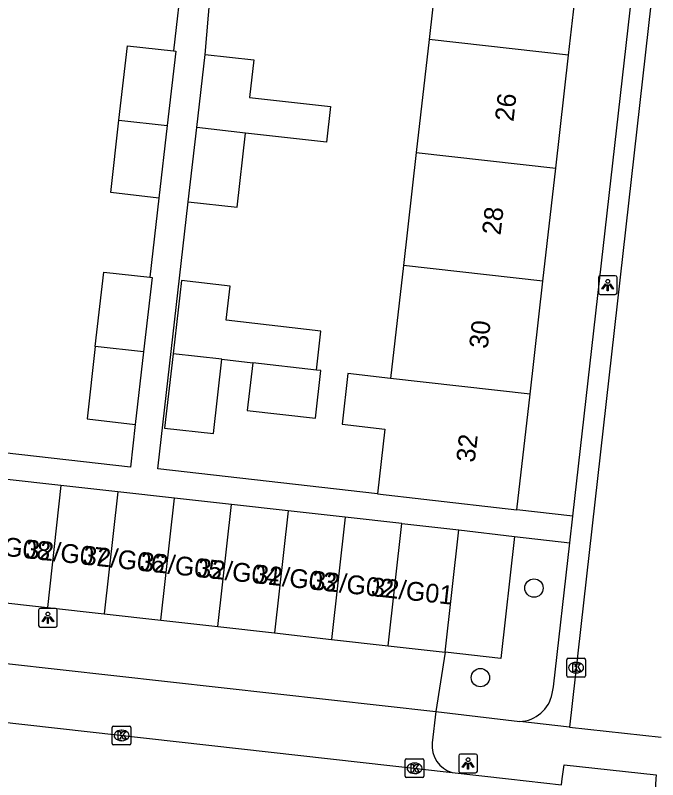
# Model space of a CAD drawing. Extents: x 161928 to 163055, y 386475 to 387428.
# Drawn here: x 162100.36 to 162134.62, y 386749.95 to 386790.68 of the extents above; entities that cross this region are included whole.
import ezdxf

# ---------------------------------------------------------------- set-up
doc = ezdxf.new("R2010")
doc.units = 0
for name, color, linetype in [('IMGEO_Boom', 7, 'Continuous'), ('IMGEO_Groenvoorziening', 7, 'Continuous'), ('IMGEO_Kolk', 7, 'Continuous'), ('IMGEO_Lichtpunt', 7, 'Continuous'), ('IMGEO_Pand', 7, 'Continuous'), ('IMGEO_Pand_nummerreeks', 7, 'Continuous'), ('IMGEO_Rijbaan_lokaal_open', 7, 'Continuous'), ('IMGEO_Voetpad_open', 7, 'Continuous')]:
    doc.layers.add(name, color=color, linetype=linetype)

msp = doc.modelspace()

# ---------------------------------------------------------------- linework, layer by layer
at = {"layer": 'IMGEO_Boom'}
for centre in [(162128.021, 386760.164), (162125.163, 386755.392)]:
    msp.add_circle(centre, 0.489, dxfattribs=at)
at = {"layer": 'IMGEO_Groenvoorziening'}
msp.add_lwpolyline([(162126.988, 386762.92), (162126.263, 386756.411), (162123.283, 386756.757)], dxfattribs=at)
at = {"layer": 'IMGEO_Kolk'}
for p, q in [((162129.77, 386755.497), (162129.77, 386756.349)), ((162129.845, 386756.423), (162130.697, 386756.423)), ((162130.258, 386756.203), (162130.283, 386756.203)), ((162130.771, 386756.349), (162130.771, 386755.497)), ((162130.697, 386755.423), (162129.845, 386755.423)), ((162130.281, 386755.643), (162130.256, 386755.643)), ((162105.606, 386752.814), (162106.458, 386752.814)), ((162105.531, 386751.888), (162105.531, 386752.74)), ((162106.019, 386752.594), (162106.044, 386752.594)), ((162106.532, 386752.74), (162106.532, 386751.888)), ((162106.042, 386752.034), (162106.017, 386752.034)), ((162106.458, 386751.814), (162105.606, 386751.814)), ((162121.155, 386750.138), (162121.155, 386750.99)), ((162121.23, 386751.064), (162122.082, 386751.064)), ((162121.643, 386750.844), (162121.668, 386750.844)), ((162122.156, 386750.99), (162122.156, 386750.138)), ((162122.082, 386750.064), (162121.23, 386750.064)), ((162121.666, 386750.284), (162121.641, 386750.284))]:
    msp.add_line(p, q, dxfattribs=at)
for points in [[(162129.77, 386755.497), (162129.77, 386756.349)], [(162129.845, 386756.423), (162130.697, 386756.423)], [(162130.091, 386756.123), (162130.214, 386756.123), (162130.214, 386755.972), (162130.344, 386756.123), (162130.508, 386756.123), (162130.362, 386755.972), (162130.515, 386755.723), (162130.363, 386755.723), (162130.278, 386755.887), (162130.214, 386755.82), (162130.214, 386755.723), (162130.091, 386755.723), (162130.091, 386756.123)], [(162130.771, 386756.349), (162130.771, 386755.497)], [(162130.697, 386755.423), (162129.845, 386755.423)], [(162105.606, 386752.814), (162106.458, 386752.814)], [(162105.531, 386751.888), (162105.531, 386752.74)], [(162105.852, 386752.514), (162105.975, 386752.514), (162105.975, 386752.363), (162106.105, 386752.514), (162106.269, 386752.514), (162106.123, 386752.363), (162106.276, 386752.114), (162106.124, 386752.114), (162106.039, 386752.278), (162105.975, 386752.211), (162105.975, 386752.114), (162105.852, 386752.114), (162105.852, 386752.514)], [(162106.532, 386752.74), (162106.532, 386751.888)], [(162106.458, 386751.814), (162105.606, 386751.814)], [(162121.155, 386750.138), (162121.155, 386750.99)], [(162121.23, 386751.064), (162122.082, 386751.064)], [(162121.476, 386750.764), (162121.599, 386750.764), (162121.599, 386750.613), (162121.729, 386750.764), (162121.893, 386750.764), (162121.747, 386750.613), (162121.9, 386750.364), (162121.748, 386750.364), (162121.663, 386750.528), (162121.599, 386750.461), (162121.599, 386750.364), (162121.476, 386750.364), (162121.476, 386750.764)], [(162122.156, 386750.99), (162122.156, 386750.138)], [(162122.082, 386750.064), (162121.23, 386750.064)]]:
    msp.add_lwpolyline(points, dxfattribs=at)
for centre, start, end in [((162129.847, 386756.347), 91.552, 178.448), ((162129.847, 386756.347), 91.552, 178.448), ((162130.695, 386756.347), 1.552, 88.448), ((162130.695, 386756.347), 1.552, 88.448), ((162129.847, 386755.499), 181.552, 268.448), ((162129.847, 386755.499), 181.552, 268.448), ((162130.695, 386755.499), 271.552, 358.448), ((162130.695, 386755.499), 271.552, 358.448), ((162105.608, 386752.738), 91.552, 178.448), ((162105.608, 386752.738), 91.552, 178.448), ((162106.456, 386752.738), 1.552, 88.448), ((162106.456, 386752.738), 1.552, 88.448), ((162105.608, 386751.89), 181.552, 268.448), ((162105.608, 386751.89), 181.552, 268.448), ((162106.456, 386751.89), 271.552, 358.448), ((162106.456, 386751.89), 271.552, 358.448), ((162121.232, 386750.988), 91.552, 178.448), ((162121.232, 386750.988), 91.552, 178.448), ((162122.08, 386750.988), 1.552, 88.448), ((162122.08, 386750.988), 1.552, 88.448), ((162121.232, 386750.14), 181.552, 268.448), ((162121.232, 386750.14), 181.552, 268.448), ((162122.08, 386750.14), 271.552, 358.448), ((162122.08, 386750.14), 271.552, 358.448)]:
    msp.add_arc(centre, 0.0765, start, end, dxfattribs=at)
for centre, major_axis, ratio, start_param, end_param in [((162130.257, 386755.923), (-0.387, 0.002), 0.722429, 4.712389, 7.853982), ((162130.282, 386755.923), (-0.39, 0.002), 0.717154, 1.570796, 4.712389), ((162106.018, 386752.314), (-0.387, 0.002), 0.722429, 4.712389, 7.853982), ((162106.043, 386752.314), (-0.39, 0.002), 0.717154, 1.570796, 4.712389), ((162121.642, 386750.564), (-0.387, 0.002), 0.722429, 4.712389, 7.853982), ((162121.667, 386750.564), (-0.39, 0.002), 0.717154, 1.570796, 4.712389)]:
    msp.add_ellipse(centre, major_axis=major_axis, ratio=ratio, start_param=start_param, end_param=end_param, dxfattribs=at)
at = {"layer": 'IMGEO_Lichtpunt'}
for p, q in [((162131.457, 386776.71), (162131.457, 386775.903)), ((162131.457, 386776.71), (162131.457, 386775.903)), ((162132.359, 386776.805), (162131.551, 386776.805)), ((162132.359, 386776.805), (162131.551, 386776.805)), ((162132.453, 386775.903), (162132.453, 386776.71)), ((162132.453, 386775.903), (162132.453, 386776.71)), ((162131.551, 386775.809), (162132.359, 386775.809)), ((162131.551, 386775.809), (162132.359, 386775.809)), ((162101.601, 386758.985), (162101.601, 386758.178)), ((162101.601, 386758.985), (162101.601, 386758.178)), ((162102.503, 386759.08), (162101.695, 386759.08)), ((162102.503, 386759.08), (162101.695, 386759.08)), ((162102.597, 386758.178), (162102.597, 386758.985)), ((162102.597, 386758.178), (162102.597, 386758.985)), ((162101.695, 386758.084), (162102.503, 386758.084)), ((162101.695, 386758.084), (162102.503, 386758.084)), ((162124.009, 386751.224), (162124.009, 386750.417)), ((162124.009, 386751.224), (162124.009, 386750.417)), ((162124.911, 386751.319), (162124.103, 386751.319)), ((162124.911, 386751.319), (162124.103, 386751.319)), ((162125.005, 386750.417), (162125.005, 386751.224)), ((162125.005, 386750.417), (162125.005, 386751.224)), ((162124.103, 386750.323), (162124.911, 386750.323)), ((162124.103, 386750.323), (162124.911, 386750.323))]:
    msp.add_line(p, q, dxfattribs=at)
for points in [[(162131.831, 386776.374), (162131.87, 386776.346), (162131.682, 386776.084), (162131.644, 386776.111), (162131.831, 386776.374)], [(162131.933, 386776.326), (162131.98, 386776.326), (162131.98, 386776.004), (162131.933, 386776.004), (162131.933, 386776.326)], [(162132.043, 386776.346), (162132.081, 386776.373), (162132.268, 386776.111), (162132.229, 386776.083), (162132.043, 386776.346)], [(162101.975, 386758.649), (162102.014, 386758.621), (162101.826, 386758.359), (162101.788, 386758.386), (162101.975, 386758.649)], [(162102.077, 386758.601), (162102.124, 386758.601), (162102.124, 386758.279), (162102.077, 386758.279), (162102.077, 386758.601)], [(162102.187, 386758.621), (162102.225, 386758.648), (162102.412, 386758.386), (162102.373, 386758.358), (162102.187, 386758.621)], [(162124.383, 386750.888), (162124.422, 386750.86), (162124.234, 386750.598), (162124.196, 386750.625), (162124.383, 386750.888)], [(162124.485, 386750.84), (162124.532, 386750.84), (162124.532, 386750.518), (162124.485, 386750.518), (162124.485, 386750.84)], [(162124.595, 386750.86), (162124.633, 386750.887), (162124.82, 386750.625), (162124.781, 386750.597), (162124.595, 386750.86)]]:
    msp.add_lwpolyline(points, dxfattribs=at)
for centre in [(162131.956, 386776.508), (162102.1, 386758.783), (162124.508, 386751.022)]:
    msp.add_circle(centre, 0.0994, dxfattribs=at)
for centre, start, end in [((162131.551, 386776.71), 90, 180), ((162131.551, 386776.71), 90, 180), ((162132.359, 386776.71), 0, 90), ((162132.359, 386776.71), 0, 90), ((162131.551, 386775.903), 180, 270), ((162131.551, 386775.903), 180, 270), ((162132.359, 386775.903), 270, 0), ((162132.359, 386775.903), 270, 360), ((162101.695, 386758.985), 90, 180), ((162101.695, 386758.985), 90, 180), ((162102.503, 386758.985), 0, 90), ((162102.503, 386758.985), 0, 90), ((162101.695, 386758.178), 180, 270), ((162101.695, 386758.178), 180, 270), ((162102.503, 386758.178), 270, 0), ((162102.503, 386758.178), 270, 360), ((162124.103, 386751.224), 90, 180), ((162124.103, 386751.224), 90, 180), ((162124.911, 386751.224), 0, 90), ((162124.911, 386751.224), 0, 90), ((162124.103, 386750.417), 180, 270), ((162124.103, 386750.417), 180, 270), ((162124.911, 386750.417), 270, 0), ((162124.911, 386750.417), 270, 360)]:
    msp.add_arc(centre, 0.0946, start, end, dxfattribs=at)
at = {"layer": 'IMGEO_Pand'}
for points in [[(162123.11, 386795.42), (162122.426, 386789.399)], [(162129.868, 386788.553), (162130.552, 386794.574)], [(162105.891, 386785.102), (162106.342, 386789.062), (162108.805, 386788.782)], [(162122.426, 386789.399), (162121.742, 386783.377)], [(162129.868, 386788.553), (162122.426, 386789.399)], [(162108.805, 386788.782), (162108.915, 386788.769), (162108.464, 386784.81)], [(162110.035, 386784.706), (162110.479, 386788.602)], [(162110.479, 386788.602), (162113.084, 386788.305), (162112.857, 386786.306), (162117.166, 386785.817), (162116.951, 386783.92), (162112.641, 386784.41)], [(162129.183, 386782.531), (162129.868, 386788.553)], [(162108.024, 386780.945), (162105.451, 386781.238), (162105.891, 386785.102)], [(162105.891, 386785.102), (162108.464, 386784.81)], [(162108.464, 386784.81), (162108.024, 386780.945)], [(162109.585, 386780.749), (162110.035, 386784.706)], [(162112.641, 386784.41), (162110.035, 386784.706)], [(162109.585, 386780.749), (162112.19, 386780.452), (162112.641, 386784.41)], [(162121.742, 386783.377), (162121.057, 386777.355)], [(162121.742, 386783.377), (162129.183, 386782.531)], [(162128.499, 386776.51), (162129.183, 386782.531)], [(162121.057, 386777.355), (162120.373, 386771.335)], [(162128.499, 386776.51), (162121.057, 386777.355)], [(162104.629, 386773.043), (162105.08, 386777.003), (162107.543, 386776.723)], [(162107.543, 386776.723), (162107.653, 386776.71), (162107.202, 386772.751)], [(162116.426, 386771.779), (162116.662, 386773.859), (162111.616, 386774.432), (162111.822, 386776.247), (162109.217, 386776.544), (162108.773, 386772.648)], [(162127.815, 386770.489), (162128.499, 386776.51)], [(162104.629, 386773.043), (162104.189, 386769.179), (162106.762, 386768.886)], [(162107.202, 386772.751), (162104.629, 386773.043)], [(162107.202, 386772.751), (162106.762, 386768.886)], [(162108.773, 386772.648), (162108.323, 386768.691), (162110.928, 386768.394), (162111.379, 386772.352)], [(162111.379, 386772.352), (162108.773, 386772.648)], [(162111.379, 386772.352), (162113.021, 386772.166)], [(162113.021, 386772.166), (162112.733, 386769.634), (162116.374, 386769.22), (162116.662, 386771.752), (162116.426, 386771.779)], [(162116.426, 386771.779), (162113.021, 386772.166)], [(162120.373, 386771.335), (162118.098, 386771.594), (162117.791, 386768.89), (162120.066, 386768.631), (162119.674, 386765.185)], [(162127.815, 386770.489), (162120.373, 386771.335)], [(162127.116, 386764.34), (162127.815, 386770.489)], [(162102.798, 386765.637), (162099.767, 386765.974)], [(162102.798, 386765.637), (162102.071, 386759.122)], [(162105.828, 386765.299), (162102.798, 386765.637)], [(162105.828, 386765.299), (162105.102, 386758.784)], [(162108.858, 386764.961), (162105.828, 386765.299)], [(162119.674, 386765.185), (162122.148, 386764.904), (162127.116, 386764.34)], [(162108.132, 386758.446), (162108.858, 386764.961)], [(162111.888, 386764.623), (162108.858, 386764.961)], [(162111.162, 386758.109), (162111.888, 386764.623)], [(162114.918, 386764.285), (162111.888, 386764.623)], [(162114.918, 386764.285), (162114.192, 386757.771)], [(162117.949, 386763.948), (162114.918, 386764.285)], [(162117.949, 386763.948), (162117.222, 386757.433)], [(162120.979, 386763.61), (162117.949, 386763.948)], [(162120.253, 386757.095), (162120.979, 386763.61)], [(162120.979, 386763.61), (162124.009, 386763.272)], [(162123.283, 386756.757), (162124.009, 386763.272)], [(162099.041, 386759.46), (162102.071, 386759.122)], [(162102.071, 386759.122), (162105.102, 386758.784)], [(162105.102, 386758.784), (162108.132, 386758.446)], [(162108.132, 386758.446), (162111.162, 386758.109)], [(162111.162, 386758.109), (162114.192, 386757.771)], [(162114.192, 386757.771), (162117.222, 386757.433)], [(162117.222, 386757.433), (162120.253, 386757.095)], [(162120.253, 386757.095), (162123.283, 386756.757)]]:
    msp.add_lwpolyline(points, dxfattribs=at)
at = {"layer": 'IMGEO_Rijbaan_lokaal_open'}
for points in [[(162136.354, 386809.876), (162129.914, 386752.746)], [(162086.964, 386754.512), (162089.619, 386754.158), (162123.662, 386750.337)], [(162129.914, 386752.746), (162134.807, 386752.229)], [(162123.662, 386750.337), (162126.661, 386750), (162129.491, 386749.686)]]:
    msp.add_lwpolyline(points, dxfattribs=at)
at = {"layer": 'IMGEO_Voetpad_open'}
for points in [[(162130.092, 386764.003), (162135.581, 386812.449)], [(162109.286, 386793.003), (162108.805, 386788.782)], [(162110.479, 386788.602), (162110.847, 386792.808)], [(162108.024, 386780.945), (162107.543, 386776.723)], [(162119.674, 386765.185), (162107.966, 386766.515), (162109.585, 386780.749)], [(162106.762, 386768.886), (162106.503, 386766.612), (162094.742, 386767.943)], [(162130.092, 386764.003), (162127.116, 386764.34)], [(162129.93, 386762.572), (162130.092, 386764.003)], [(162124.009, 386763.272), (162126.988, 386762.92)], [(162126.988, 386762.92), (162129.93, 386762.572)], [(162128.987, 386754.54), (162129.066, 386754.9), (162129.93, 386762.572)], [(162088.426, 386757.42), (162122.784, 386753.584)], [(162123.283, 386756.757), (162122.784, 386753.584)], [(162122.784, 386753.584), (162122.596, 386751.923)], [(162122.784, 386753.584), (162127.26, 386753.058)], [(162129.914, 386752.746), (162127.26, 386753.058)], [(162129.491, 386749.686), (162129.532, 386750), (162129.629, 386750.754), (162134.53, 386750.22), (162134.518, 386750), (162134.473, 386749.133)]]:
    msp.add_lwpolyline(points, dxfattribs=at)
for centre, radius, start, end in [((162127.196, 386754.88), 1.824, 272.0257, 349.2425), ((162124.051, 386751.75), 1.465, 173.1992, 254.6133)]:
    msp.add_arc(centre, radius, start, end, dxfattribs=at)

# ---------------------------------------------------------------- texts
at = {"layer": 'IMGEO_Pand_nummerreeks'}
for s, rotation, p in [('26', 83.5165, (162126.927, 386784.989)), ('28', 83.5165, (162126.239, 386778.939)), ('30', 83.5165, (162125.551, 386772.886)), ('32', 83.5143, (162124.862, 386766.827)), ('32/G08', 353.7671, (162097.828, 386762.096)), ('32/G07', 353.7671, (162100.877, 386761.763)), ('32/G06', 353.7671, (162103.929, 386761.43)), ('32/G05', 353.7671, (162106.981, 386761.096)), ('32/G04', 353.7671, (162110.033, 386760.763)), ('32/G03', 353.7671, (162113.085, 386760.43)), ('32/G02', 353.7671, (162116.131, 386760.097)), ('32/G01', 353.7671, (162119.299, 386759.751))]:
    msp.add_text(s, height=1, rotation=rotation, dxfattribs=at).set_placement(p)

doc.saveas('drawing.dxf')
